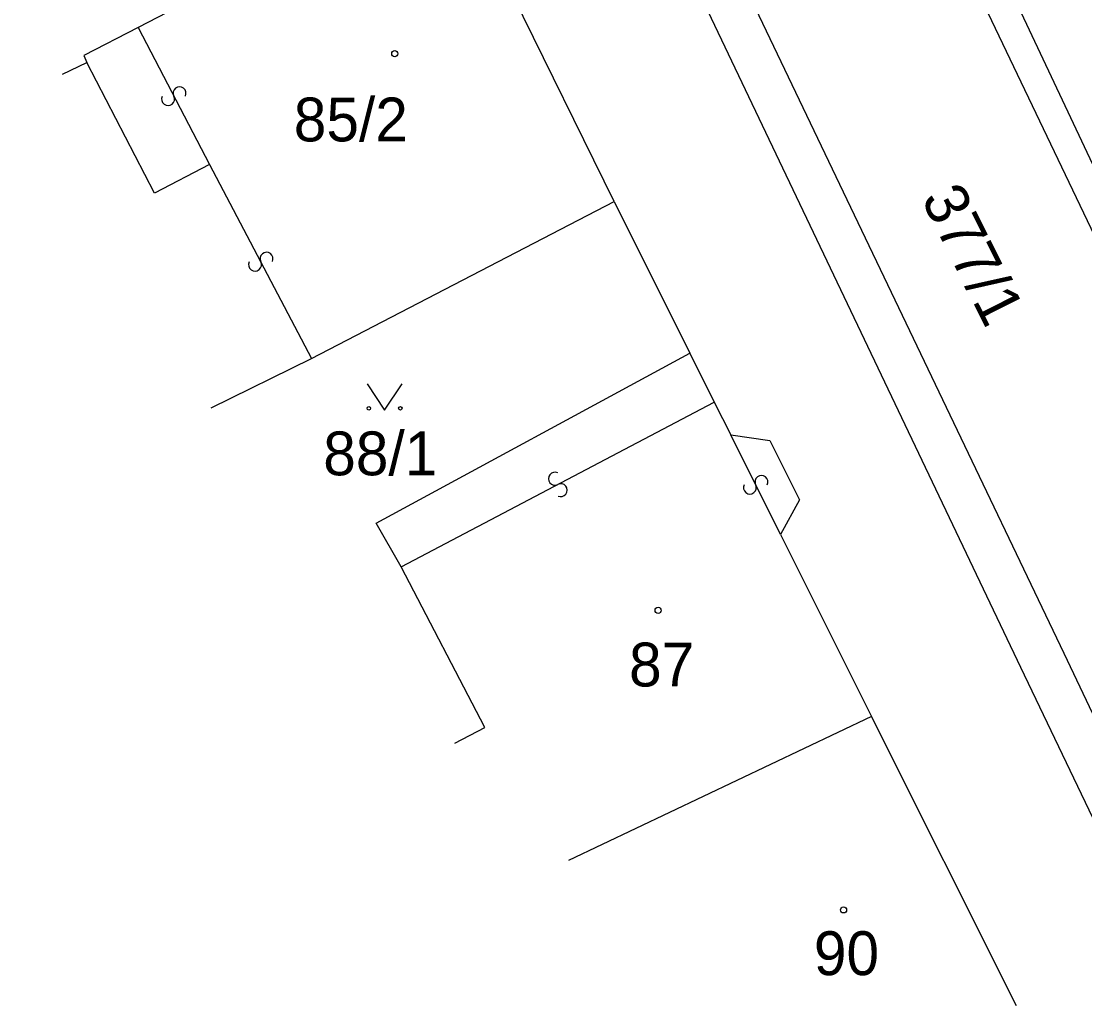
# Model space of a CAD drawing. Extents: x -595692 to -595466, y -1166896 to -1166788.
# Drawn here: x -595674.15 to -595643.83, y -1166896.32 to -1166868.26 of the extents above; entities that cross this region are included whole.
import ezdxf

# ---------------------------------------------------------------- set-up
doc = ezdxf.new("R2010")
doc.units = 0
doc.layers.add('DKM Holásky M 1_500', color=7, linetype='Continuous')

msp = doc.modelspace()

# ---------------------------------------------------------------- linework, layer by layer
at = {"layer": 'DKM Holásky M 1_500'}
for points in [[(-595644.41, -1166886.28), (-595673.03, -1166826.45)], [(-595674.15, -1166826.88), (-595645.66, -1166886.67)], [(-595638.25, -1166883.67), (-595661.59, -1166834.17)], [(-595662.54, -1166834.67), (-595638.93, -1166884.03)], [(-595661.94, -1166863.83), (-595670.82, -1166868.43)], [(-595657.24, -1166873.39), (-595660.12, -1166867.53)], [(-595670.82, -1166868.43), (-595672.37, -1166869.23)], [(-595670.82, -1166868.43), (-595668.78, -1166872.34)], [(-595672.974, -1166869.759), (-595672.28, -1166869.43)], [(-595672.37, -1166869.23), (-595672.28, -1166869.43)], [(-595670.35, -1166873.16), (-595672.28, -1166869.43)], [(-595668.78, -1166872.34), (-595670.35, -1166873.16)], [(-595668.78, -1166872.34), (-595665.87, -1166877.87)], [(-595665.87, -1166877.87), (-595657.24, -1166873.39)], [(-595657.24, -1166873.39), (-595655.09, -1166877.72)], [(-595668.736, -1166879.279), (-595665.87, -1166877.87)], [(-595664.03, -1166882.56), (-595655.09, -1166877.72)], [(-595655.09, -1166877.72), (-595654.39, -1166879.11)], [(-595664.29, -1166878.59), (-595663.79, -1166879.34), (-595663.29, -1166878.59)], [(-595663.32, -1166883.81), (-595654.39, -1166879.11)], [(-595654.39, -1166879.11), (-595653.92, -1166880.05)], [(-595652.5, -1166882.89), (-595653.92, -1166880.05)], [(-595653.92, -1166880.05), (-595652.81, -1166880.21)], [(-595652.81, -1166880.21), (-595651.96, -1166881.9)], [(-595651.96, -1166881.9), (-595652.5, -1166882.89)], [(-595663.32, -1166883.81), (-595664.03, -1166882.56)], [(-595652.5, -1166882.89), (-595649.91, -1166888.08)], [(-595660.93, -1166888.39), (-595663.32, -1166883.81)], [(-595641.15, -1166893.14), (-595644.41, -1166886.28)], [(-595645.66, -1166886.67), (-595642.3, -1166893.67)], [(-595649.91, -1166888.08), (-595658.547, -1166892.178)], [(-595645.769, -1166896.323), (-595649.91, -1166888.08)], [(-595661.792, -1166888.837), (-595660.93, -1166888.39)]]:
    msp.add_lwpolyline(points, dxfattribs=at)
for centre, radius in [((-595663.5, -1166869.18), 0.0875), ((-595664.24, -1166879.29), 0.05), ((-595663.34, -1166879.29), 0.05), ((-595655.99, -1166885.049), 0.0875), ((-595650.705, -1166893.591), 0.0875)]:
    msp.add_circle(centre, radius, dxfattribs=at)
for centre, radius, start, end in [((-595669.636, -1166870.306), 0.184, 334.1204, 207.1229), ((-595669.964, -1166870.473), 0.184, 154.9656, 26.2858), ((-595667.157, -1166875.026), 0.184, 334.7089, 207.2654), ((-595667.484, -1166875.194), 0.184, 154.9656, 26.5646), ((-595658.934, -1166881.296), 0.184, 64.6552, 297.1237), ((-595653.044, -1166881.39), 0.185, 333.9925, 206.2951), ((-595658.766, -1166881.624), 0.184, 244.9663, 117.1251), ((-595653.375, -1166881.55), 0.184, 153.8503, 25.8666)]:
    msp.add_arc(centre, radius, start, end, dxfattribs=at)

# ---------------------------------------------------------------- texts
for s, p in [('85/2', (-595666.38, -1166871.68)), ('88/1', (-595665.54, -1166881.2)), ('87', (-595656.82, -1166887.22)), ('90', (-595651.55, -1166895.45))]:
    msp.add_text(s, height=1.25, dxfattribs=at).set_placement(p)
msp.add_text('377/1', height=1.25, rotation=296.6821, dxfattribs=at).set_placement((-595648.506, -1166873.311))

doc.saveas('drawing.dxf')
